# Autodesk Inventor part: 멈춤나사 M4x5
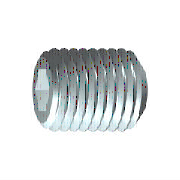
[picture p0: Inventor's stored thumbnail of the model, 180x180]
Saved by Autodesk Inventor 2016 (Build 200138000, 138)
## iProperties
IsCustomPart: 1
Created: 2012-02
Part Number: 멈춤나사 M4x5
Material: 강철, 연강
Description: 6각 소켓 머리 없는 멈춤 나사
Document SubType Name: Modeling
Standard: KS B 1028
Designer: mduedu
Standards Organization: KS
Language: ko-KR
Size Designation: 납작점M4x5
Categories: <MemberInstance><Categories><Category DisplayName="조임쇠" InternalName="e4da775c-781d-43d5-af7c-5136215cf5a6" Mnemonic="FSTN"><Category DisplayName="볼트" InternalN
Density: 1 g/cm^3
Appearance: 노란색
Author: mduedu
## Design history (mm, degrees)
sketch "스케치1"
  geometry: L1 (0, 0)-(1.833, 0); L2 (5, 1.155)-(5, 2); L3 (5, 2)-(0, 2); L4 (5, 1.155)-(2.5, 1.155); L5 (2.5, 1.155)-(1.833, 0); L6 (0, -0.4)-(0, 2.4) reference; L7 (0, 2)-(0, 0)
  constraints: 13 end point, 3 parallel, 1 collinear, 1 perpendicular, 1 point on line
  dimensions: "d0" = 2.5 distance of L2.start L4.end (= INTI); "d1" = 60 deg angle of L5 L1; "d2" = 4 diameter of L3 L1 (= NND); "d3" = 2.3094 diameter of L4 L1 (= 1.1547 x SW); "d5" = 5 distance from line of L2 L3.end (= NLG)
revolve "본체" sketch "스케치1" stored, may be unused: angle "d6" = 90 deg
sketch "스케치2"
  geometry: L1 (-0.577, 1)-(0.577, 1); L2 (0.577, 1)-(1.155, 0); L3 (1.155, 0)-(0.577, -1); L4 (0.577, -1)-(-0.577, -1); L5 (-0.577, -1)-(-1.155, 0); L6 (-1.155, 0)-(-0.577, 1); A1 r 1.155 centre (0, 0) between (-0.577, 1) and (0.577, 1) reference; 2 further points
  constraints: 12 end point, 2 point on circle, 1 coincident, 1 horizontal, 11 other
extrude "슬롯" join sketch "스케치2" taper "d9" = 0 deg; stored distance "d21" = 10
workaxis "Work Axis1"
workplane "Work Plane1"
body "Solid1"
chamfer "모따기1" distance "d7" = 0.42941 (= -0.5 x GD1 + 0.5 x NND); stored, may be unused: angle "d8" = 45 deg (= FAWI), second distance "d29" = 0.42941 (= -0.5 x GD1 + 0.5 x NND)
feature "스레드" dims "d11" = 5 (= NLG), "d12" = 0
chamfer "모따기2" distance "d13" = 0.42941 (= -0.5 x GD1 + 0.5 x NND); stored, may be unused: angle "d14" = 45 deg (= FAWI), second distance "d30" = 0.42941 (= -0.5 x GD1 + 0.5 x NND)
other parameters: "NND" = 4 [user parameter; used in 5 equation terms], "NLG" = 5 [user parameter; used in 2 equation terms], "INTI" = 2.5 [user parameter; used in 1 equation term], "FAWI" = 45 deg [user parameter; used in 2 equation terms], "SW" = 2 [user parameter; used in 2 equation terms], "GD1" = 3.14117 (= THREADDIA - 1.2269 x PTC) [user parameter; used in 4 equation terms], "d4" = 0, "FAWI1" = 45 deg [user parameter], "d15" = 0, "d31" = 0, "GUL" = 0.42941 (= 0.61345 x PTC) [user parameter], "SPD" = 2.5 [user parameter], "TPU" = 14.28571 (computed from PTC) [user parameter], "TOA" = 30 deg [user parameter], "THREADDIA" = 4 [user parameter; used in 1 equation term], "PTC" = 0.7 [user parameter; used in 4 equation terms], "GAL" = 0.42941 (= 0.61345 x PTC) [user parameter], "E0" = 2.31 (= 1.155 x SW) [user parameter]
